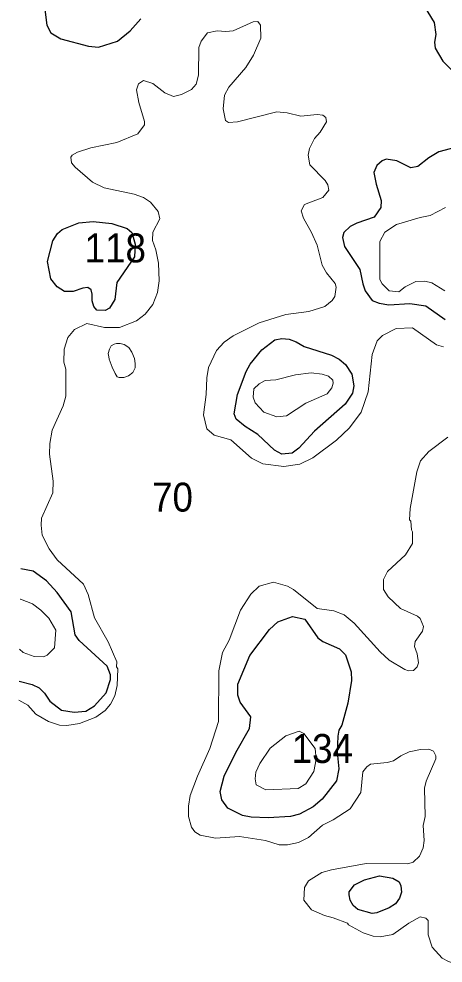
# Model space of a CAD drawing. Extents: x 673.6 to 698.9, y 7012 to 7040.1.
# Drawn here: x 673.954 to 675.127, y 7034.12 to 7036.731 of the extents above; entities that cross this region are included whole.
import ezdxf

# ---------------------------------------------------------------- set-up
doc = ezdxf.new("R2010")
doc.units = 0
doc.header["$LTSCALE"] = 0.032
doc.layers.add('1', color=7, linetype='Continuous', lineweight=25)
doc.layers.add('2', color=7, linetype='Continuous', lineweight=13)
doc.layers.add('21', color=7, linetype='Continuous')

msp = doc.modelspace()

# ---------------------------------------------------------------- linework, layer by layer
at = {"layer": '1'}
for points in [[(675.0509, 7036.8618), (675.0484, 7036.8407), (675.0501, 7036.8138), (675.0648, 7036.7824), (675.1024, 7036.7208), (675.1066, 7036.6871)], [(674.0211, 7036.7931), (674.0316, 7036.7129), (674.0425, 7036.6921), (674.0697, 7036.6759), (674.1469, 7036.6548), (674.1746, 7036.652), (674.2267, 7036.6687), (674.2617, 7036.6975), (674.2909, 7036.7309)], [(675.1066, 7036.6871), (675.1033, 7036.666), (675.1051, 7036.6494), (675.1262, 7036.6135), (675.1542, 7036.586)], [(675.1773, 7036.3794), (675.1149, 7036.3633), (675.087, 7036.3469), (675.0569, 7036.3222), (675.0375, 7036.3191), (674.9993, 7036.3384), (674.9699, 7036.3426), (674.9581, 7036.3381), (674.944, 7036.3255), (674.9358, 7036.3055), (674.9417, 7036.2732), (674.9554, 7036.2286), (674.9547, 7036.2092), (674.9362, 7036.1825), (674.8882, 7036.1661), (674.8701, 7036.1562), (674.8522, 7036.1399), (674.8487, 7036.1265), (674.854, 7036.1013), (674.8963, 7036.0379), (674.9046, 7035.9985), (674.9118, 7035.9791), (674.9312, 7035.9523), (674.9501, 7035.9442), (674.9764, 7035.9402), (675.0352, 7035.9434), (675.0791, 7035.9373), (675.1325, 7035.8997)], [(673.9549, 7034.8997), (673.9907, 7034.8907), (674.0104, 7034.8808), (674.0252, 7034.8661), (674.0395, 7034.8445), (674.0716, 7034.8192), (674.1067, 7034.8136), (674.139, 7034.8167), (674.1627, 7034.831), (674.1953, 7034.867), (674.2077, 7034.9043), (674.2076, 7034.9174), (674.198, 7034.9407), (674.1204, 7035.0117), (674.1099, 7035.0281), (674.0984, 7035.0912), (674.06, 7035.1443), (674.0301, 7035.1767), (673.9934, 7035.2036), (673.9591, 7035.2098)]]:
    msp.add_lwpolyline(points, dxfattribs=at)
for points in [[(674.2659, 7036.1404), (674.2759, 7036.1081), (674.274, 7036.0732), (674.2245, 7036.0022), (674.2191, 7035.9545), (674.2048, 7035.9305), (674.1929, 7035.9245), (674.1693, 7035.9251), (674.1616, 7035.9352), (674.1568, 7035.9508), (674.1564, 7035.9697), (674.1541, 7035.9819), (674.1447, 7035.9881), (674.1311, 7035.986), (674.1038, 7035.9766), (674.08, 7035.9773), (674.0598, 7035.9895), (674.0425, 7036.0121), (674.0331, 7036.0603), (674.0475, 7036.1168), (674.0609, 7036.1376), (674.0736, 7036.1484), (674.1197, 7036.1671), (674.1592, 7036.1702), (674.2106, 7036.1645), (674.2534, 7036.1514)], [(674.8561, 7035.665), (674.7716, 7035.5912), (674.7279, 7035.5442), (674.7092, 7035.5303), (674.6813, 7035.5273), (674.6605, 7035.5384), (674.6151, 7035.5813), (674.5797, 7035.6035), (674.555, 7035.6241), (674.5488, 7035.6391), (674.5587, 7035.6923), (674.582, 7035.7561), (674.5937, 7035.7763), (674.6259, 7035.816), (674.6617, 7035.8432), (674.6811, 7035.8472), (674.7011, 7035.8455), (674.7204, 7035.8382), (674.7428, 7035.8249), (674.8187, 7035.8006), (674.8391, 7035.7895), (674.8568, 7035.7749), (674.8749, 7035.7486), (674.8798, 7035.7159), (674.8764, 7035.6962)], [(674.8471, 7034.7778), (674.8388, 7034.7642), (674.8354, 7034.7474), (674.8339, 7034.703), (674.8387, 7034.657), (674.8323, 7034.6241), (674.7926, 7034.5734), (674.7675, 7034.5521), (674.7295, 7034.532), (674.7052, 7034.5259), (674.6429, 7034.5218), (674.5959, 7034.5234), (674.5727, 7034.5281), (674.532, 7034.5487), (674.5148, 7034.5711), (674.5102, 7034.5942), (674.5214, 7034.6372), (674.554, 7034.7026), (674.5914, 7034.7691), (674.595, 7034.801), (674.5654, 7034.8415), (674.5594, 7034.8612), (674.5598, 7034.8917), (674.5928, 7034.9704), (674.6468, 7035.042), (674.6704, 7035.0641), (674.7103, 7035.078), (674.7447, 7035.0708), (674.7807, 7035.0195), (674.7942, 7035.0092), (674.8407, 7034.989), (674.8567, 7034.972), (674.8724, 7034.9254), (674.8733, 7034.9018), (674.8635, 7034.8385)], [(674.9436, 7034.2588), (674.9307, 7034.2575), (674.8907, 7034.2684), (674.8781, 7034.2798), (674.8695, 7034.2941), (674.8669, 7034.3085), (674.867, 7034.3175), (674.8819, 7034.3362), (674.9094, 7034.35), (674.9509, 7034.3615), (674.9883, 7034.3549), (675.0052, 7034.3444), (675.0103, 7034.3338), (675.0115, 7034.3162), (675.0063, 7034.2993), (674.995, 7034.284), (674.9779, 7034.273)]]:
    msp.add_lwpolyline(points, close=True, dxfattribs=at)
at = {"layer": '2'}
for points in [[(674.6023, 7036.6299), (674.6226, 7036.6773), (674.6218, 7036.7132), (674.6143, 7036.7231), (674.6022, 7036.7224), (674.5466, 7036.6972), (674.5266, 7036.6954), (674.5018, 7036.6978), (674.4753, 7036.6921), (674.4577, 7036.6693), (674.4512, 7036.6516), (674.4509, 7036.5753), (674.444, 7036.5498), (674.4311, 7036.5358), (674.4039, 7036.5214), (674.3813, 7036.5163), (674.3576, 7036.5259), (674.324, 7036.5521), (674.2989, 7036.5603), (674.2851, 7036.5514), (674.2792, 7036.5343), (674.2856, 7036.4998), (674.3014, 7036.447), (674.3012, 7036.4374), (674.2828, 7036.4125), (674.2251, 7036.3887), (674.1534, 7036.374), (674.1157, 7036.3625), (674.1016, 7036.354), (674.0977, 7036.3483), (674.0994, 7036.3327), (674.1094, 7036.3203), (674.1579, 7036.2792), (674.1903, 7036.2637), (674.2731, 7036.2459), (674.2986, 7036.2364), (674.318, 7036.2241), (674.3394, 7036.198), (674.344, 7036.1777), (674.3247, 7036.1405), (674.3235, 7036.118), (674.3327, 7036.0922), (674.3398, 7036.055), (674.3416, 7036.0064), (674.3376, 7035.9737), (674.3244, 7035.9413), (674.3036, 7035.9144), (674.2794, 7035.8954), (674.2325, 7035.8776), (674.1912, 7035.8776), (674.1419, 7035.8883), (674.1081, 7035.8714), (674.0895, 7035.8498), (674.0795, 7035.8177), (674.0779, 7035.7812), (674.0843, 7035.7618), (674.0835, 7035.6879), (674.0765, 7035.6606), (674.0465, 7035.5939), (674.0399, 7035.5569), (674.0385, 7035.5273), (674.049, 7035.4525), (674.0482, 7035.4203), (674.0169, 7035.3498), (674.0154, 7035.3309), (674.0185, 7035.3035), (674.0376, 7035.2653), (674.0601, 7035.2354), (674.133, 7035.1682), (674.1457, 7035.1391), (674.1633, 7035.0748), (674.2013, 7035.0088), (674.2248, 7034.9532), (674.2242, 7034.9396), (674.2274, 7034.9334), (674.2257, 7034.8872), (674.2195, 7034.859), (674.2074, 7034.8364), (674.1925, 7034.8187), (674.1668, 7034.7997), (674.1219, 7034.7822), (674.0871, 7034.7774), (674.066, 7034.7782), (674.0357, 7034.7878), (674.0009, 7034.8084), (673.9788, 7034.8328), (673.9541, 7034.8474)], [(674.5253, 7036.4494), (674.5184, 7036.4822), (674.5228, 7036.52), (674.5344, 7036.5414), (674.5811, 7036.5961), (674.6023, 7036.6299)], [(675.1277, 7035.8235), (675.1087, 7035.8292), (675.0423, 7035.876), (674.9968, 7035.8744), (674.959, 7035.8548), (674.9446, 7035.8404), (674.9307, 7035.8023), (674.9201, 7035.6993), (674.9004, 7035.6436), (674.8684, 7035.5999), (674.8318, 7035.566), (674.7667, 7035.5171), (674.731, 7035.4999), (674.6865, 7035.493), (674.6281, 7035.5007), (674.5971, 7035.5163), (674.5401, 7035.5664), (674.494, 7035.5793), (674.4737, 7035.5976), (674.4641, 7035.6363), (674.4723, 7035.6918), (674.474, 7035.7378), (674.4786, 7035.7667), (674.5, 7035.8142), (674.5219, 7035.8369), (674.5465, 7035.8546), (674.6185, 7035.89), (674.6925, 7035.913), (674.7553, 7035.9214), (674.7999, 7035.9352), (674.8201, 7035.952), (674.8271, 7035.9633), (674.8312, 7035.9885), (674.8287, 7035.9992), (674.8048, 7036.0283), (674.7927, 7036.0495), (674.7783, 7036.1047), (674.7631, 7036.1398), (674.7409, 7036.1797), (674.7345, 7036.2), (674.7436, 7036.2178), (674.794, 7036.2365), (674.8108, 7036.2569), (674.8082, 7036.2721), (674.8012, 7036.2841), (674.7583, 7036.3267), (674.7534, 7036.354), (674.7571, 7036.3725), (674.7716, 7036.3998), (674.7872, 7036.4178), (674.8041, 7036.446), (674.8024, 7036.4579), (674.7946, 7036.4643), (674.7787, 7036.4667), (674.7337, 7036.462), (674.6958, 7036.4709), (674.6675, 7036.4734), (674.5581, 7036.4456), (674.5337, 7036.4439), (674.5253, 7036.4494)], [(675.1336, 7036.2093), (675.091, 7036.1869), (675.0639, 7036.1817), (674.9982, 7036.162), (674.9661, 7036.1412), (674.9523, 7036.1149), (674.9523, 7036.0102), (674.9584, 7035.9983), (674.9775, 7035.979), (675.0047, 7035.9764), (675.0216, 7035.9895), (675.0517, 7036.0047), (675.0766, 7036.0052), (675.0954, 7036.001), (675.1321, 7035.9784)], [(675.0375, 7035.3421), (675.0344, 7035.3452), (675.036, 7035.3772), (675.0538, 7035.4781), (675.0646, 7035.5084), (675.0875, 7035.5348), (675.1402, 7035.5744)], [(674.973, 7035.2031), (675.0231, 7035.2485), (675.0423, 7035.2799), (675.0425, 7035.3121), (675.0394, 7035.3184), (675.0375, 7035.3421)], [(675.1241, 7034.1341), (675.0962, 7034.1642), (675.0854, 7034.1985), (675.0854, 7034.2376), (675.0789, 7034.2447), (675.0635, 7034.2478), (675.0321, 7034.2305), (674.9883, 7034.1993), (674.9526, 7034.1932), (674.9338, 7034.1948), (674.9058, 7034.2039), (674.8651, 7034.2261), (674.8624, 7034.2301), (674.8234, 7034.2455), (674.7993, 7034.2513), (674.763, 7034.2675), (674.7419, 7034.2945), (674.7436, 7034.329), (674.7552, 7034.3478), (674.792, 7034.3705), (674.8181, 7034.3782), (674.9141, 7034.3952), (675.0298, 7034.3945), (675.0438, 7034.3993), (675.062, 7034.4155), (675.0721, 7034.4392), (675.0746, 7034.4594), (675.0721, 7034.501), (675.0771, 7034.5252), (675.0756, 7034.6038), (675.0801, 7034.6228), (675.1064, 7034.6847), (675.1066, 7034.6932), (675.1006, 7034.706), (675.0876, 7034.7116), (675.0646, 7034.7108), (675.0332, 7034.704), (675.0098, 7034.6935), (674.9893, 7034.6794), (674.9719, 7034.6747), (674.9259, 7034.6697), (674.9158, 7034.6629), (674.9048, 7034.6486), (674.8997, 7034.592), (674.8697, 7034.5471), (674.8228, 7034.5159), (674.7938, 7034.5017), (674.7544, 7034.4672), (674.7275, 7034.4532), (674.697, 7034.4474), (674.6741, 7034.4471), (674.636, 7034.4595), (674.5636, 7034.47), (674.4975, 7034.4652), (674.4554, 7034.4734), (674.4401, 7034.4833), (674.4313, 7034.4963), (674.423, 7034.5252), (674.423, 7034.5538), (674.4276, 7034.5837), (674.4475, 7034.6373), (674.4824, 7034.7139), (674.5058, 7034.7885), (674.5069, 7034.9281), (674.5171, 7034.979), (674.535, 7035.0131), (674.5667, 7035.0959), (674.5951, 7035.1399), (674.6187, 7035.1626), (674.658, 7035.1734), (674.6967, 7035.1622), (674.7133, 7035.1533), (674.7786, 7035.1006), (674.825, 7035.0939), (674.8533, 7035.0832), (674.8812, 7035.0596), (674.9531, 7034.9809), (674.9779, 7034.9578), (675.0215, 7034.9317), (675.0315, 7034.9286), (675.0449, 7034.9295), (675.0552, 7034.9395), (675.0589, 7034.9503), (675.0551, 7034.9756), (675.0476, 7034.9952), (675.0492, 7035.0096), (675.0701, 7035.0379), (675.0729, 7035.0507), (675.0634, 7035.0733), (675.0563, 7035.0797), (675.0087, 7035.1008), (674.975, 7035.1326), (674.9621, 7035.1526), (674.962, 7035.1805), (674.973, 7035.2031)], [(673.9561, 7034.9883), (673.9659, 7034.979), (673.9966, 7034.9682), (674.0221, 7034.9672), (674.0319, 7034.9712), (674.0527, 7034.9914), (674.0564, 7035.0408), (674.0365, 7035.0735), (674.0145, 7035.0962), (673.9919, 7035.1134), (673.9587, 7035.1259), (673.958, 7035.1262)], [(675.2148, 7034.0533), (675.2178, 7034.0789), (675.2008, 7034.0998), (675.1879, 7034.108), (675.1415, 7034.1247), (675.1241, 7034.1341)]]:
    msp.add_lwpolyline(points, dxfattribs=at)
for points in [[(674.2039, 7035.7902), (674.2121, 7035.768), (674.2202, 7035.7504), (674.2261, 7035.7409), (674.2316, 7035.7389), (674.2444, 7035.7389), (674.2571, 7035.7435), (674.2692, 7035.7526), (674.2754, 7035.7657), (674.276, 7035.7781), (674.2741, 7035.7921), (674.2666, 7035.8094), (674.2577, 7035.8221), (674.2447, 7035.8306), (674.2343, 7035.8336), (674.2241, 7035.8336), (674.2173, 7035.8316), (674.2095, 7035.8264), (674.2046, 7035.8176), (674.2013, 7035.8058), (674.2029, 7035.796)], [(674.6645, 7035.7331), (674.7188, 7035.7461), (674.7622, 7035.7519), (674.7926, 7035.7488), (674.8103, 7035.7429), (674.822, 7035.7317), (674.823, 7035.7238), (674.819, 7035.7104), (674.8061, 7035.6942), (674.747, 7035.6683), (674.6935, 7035.6332), (674.6668, 7035.6304), (674.6309, 7035.6433), (674.6069, 7035.6688), (674.6022, 7035.685), (674.6038, 7035.7081), (674.6188, 7035.7219), (674.6354, 7035.7306)], [(674.7264, 7034.603), (674.6364, 7034.5996), (674.6105, 7034.6131), (674.6069, 7034.63), (674.6092, 7034.648), (674.6202, 7034.6722), (674.6492, 7034.7143), (674.6925, 7034.7486), (674.7294, 7034.761), (674.7423, 7034.7546), (674.7728, 7034.7139), (674.7764, 7034.6838), (674.7692, 7034.6498), (674.7477, 7034.6158)]]:
    msp.add_lwpolyline(points, close=True, dxfattribs=at)

# ---------------------------------------------------------------- texts
at = {"layer": '21', "width": 0.95}
for s, p in [('118', (674.1358, 7036.0574)), ('70', (674.3223, 7035.3684)), ('134', (674.7082, 7034.6735))]:
    msp.add_text(s, height=0.08, dxfattribs=at).set_placement(p)

doc.saveas('drawing.dxf')
